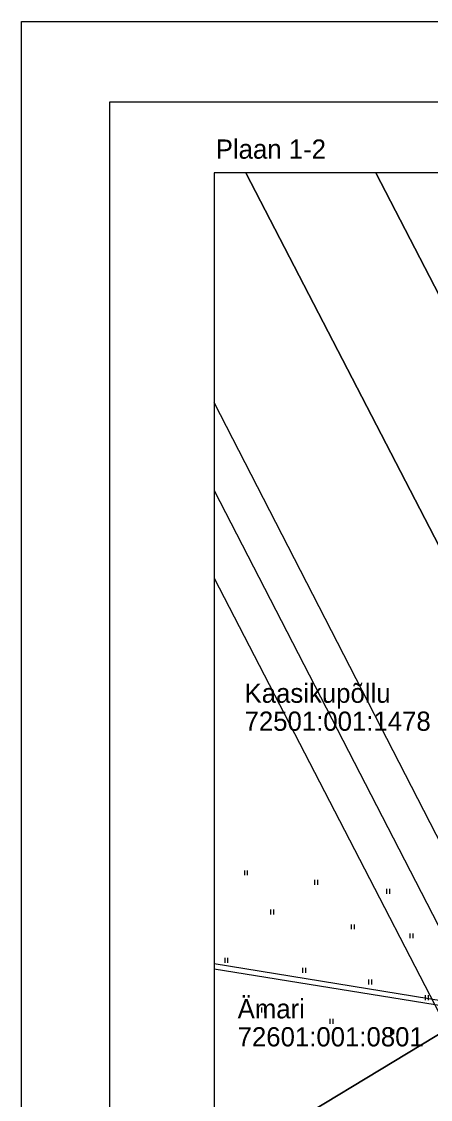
# Model space of a CAD drawing. Extents: x 532656 to 533339, y 6581345 to 6581629.
# Drawn here: x 532655.8 to 532719.5, y 6581439.6 to 6581607.7 of the extents above; entities that cross this region are included whole.
import ezdxf

# ---------------------------------------------------------------- set-up
doc = ezdxf.new("R2010")
doc.units = 0
for name, color, linetype in [('HALJASTUS', 7, 'Continuous'), ('KPOHULIIN', 7, 'Continuous'), ('PIIR', 7, 'Continuous'), ('PR_SIDE', 7, 'Continuous'), ('VORMISTUS_1', 7, 'Continuous')]:
    doc.layers.add(name, color=color, linetype=linetype)

msp = doc.modelspace()

# ---------------------------------------------------------------- linework, layer by layer
at = {"layer": 'HALJASTUS'}
for p, q in [((532690.51, 6581475.33), (532690.51, 6581474.57)), ((532690.96, 6581475.33), (532690.96, 6581474.57)), ((532701.44, 6581473.85), (532701.44, 6581473.09)), ((532701.89, 6581473.85), (532701.89, 6581473.09)), ((532712.66, 6581472.45), (532712.66, 6581471.69)), ((532713.12, 6581472.45), (532713.12, 6581471.69)), ((532694.6, 6581469.2), (532694.6, 6581468.44)), ((532695.05, 6581469.2), (532695.05, 6581468.44)), ((532707.15, 6581466.91), (532707.15, 6581466.14)), ((532707.61, 6581466.91), (532707.61, 6581466.14)), ((532716.31, 6581465.5), (532716.31, 6581464.74)), ((532716.77, 6581465.5), (532716.77, 6581464.74)), ((532687.45, 6581461.69), (532687.45, 6581460.93)), ((532687.9, 6581461.69), (532687.9, 6581460.93)), ((532699.56, 6581460.13), (532699.56, 6581459.37)), ((532700.01, 6581460.13), (532700.01, 6581459.37)), ((532709.85, 6581458.31), (532709.85, 6581457.55)), ((532710.31, 6581458.31), (532710.31, 6581457.55)), ((532718.67, 6581455.86), (532718.67, 6581455.1)), ((532719.13, 6581455.86), (532719.13, 6581455.1)), ((532693.17, 6581453.94), (532693.17, 6581453.18)), ((532693.63, 6581453.94), (532693.63, 6581453.18)), ((532703.85, 6581452.16), (532703.85, 6581451.4)), ((532704.3, 6581452.16), (532704.3, 6581451.4)), ((532713.26, 6581450.52), (532713.26, 6581449.76)), ((532713.72, 6581450.52), (532713.72, 6581449.76))]:
    msp.add_line(p, q, dxfattribs=at)
at = {"layer": 'KPOHULIIN'}
for p, q in [((532761.68, 6581400.4), (532685.8, 6581548.33)), ((532685.8, 6581534.57), (532754.86, 6581400.4)), ((532685.8, 6581520.92), (532748.01, 6581400.4))]:
    msp.add_line(p, q, dxfattribs=at)
at = {"layer": 'PIIR'}
for points in [[(532690.74, 6581584.15), (532751.03, 6581467.56), (532726.7, 6581453.3), (532685.8, 6581459.92)], [(532710.97, 6581584.15), (532766.54, 6581476.67), (532751.03, 6581467.56), (532690.74, 6581584.15)], [(532997.7, 6581510.35), (532853.02, 6581527.38), (532766.54, 6581476.67), (532710.97, 6581584.15)], [(532685.8, 6581428.57), (532726.7, 6581453.3), (532685.8, 6581459.92)], [(532688.64, 6581400.4), (532765.26, 6581446.64), (532740.99, 6581450.83), (532726.7, 6581453.3), (532685.8, 6581428.57)]]:
    msp.add_lwpolyline(points, dxfattribs=at)
at = {"layer": 'PR_SIDE'}
msp.add_lwpolyline([(532685.8, 6581460.81), (532752.67, 6581449.89), (532752.64, 6581449.86), (532756.24, 6581452.32), (532771.22, 6581460.37), (532800.17, 6581478.56), (532838.61, 6581500.05), (532844.07, 6581501.83), (532856.14, 6581503.74), (532864.29, 6581503.71), (532878.64, 6581501.24), (532905.33, 6581498.02), (532934.77, 6581493.52), (532940.7, 6581499.68), (532975.83, 6581495.55), (532984.66, 6581494.39), (532991.64, 6581492.92), (533009.76, 6581491.73), (533020.32, 6581490.23)], dxfattribs=at)
at = {"layer": 'VORMISTUS_1'}
for points in [[(532655.8, 6581607.74), (533027.05, 6581607.74), (533027.05, 6581345.24), (532655.8, 6581345.24)], [(532669.55, 6581357.74), (532669.55, 6581595.24), (533013.3, 6581595.24), (533013.3, 6581357.74)], [(532669.55, 6581595.24), (533013.3, 6581595.24), (533013.3, 6581357.74), (532669.55, 6581357.74)], [(532997.7, 6581400.4), (532997.7, 6581584.15), (532685.8, 6581584.15), (532685.8, 6581400.4)]]:
    msp.add_lwpolyline(points, close=True, dxfattribs=at)
for points in [[(532685.8, 6581584.15), (532685.8, 6581400.4)], [(532997.7, 6581584.15), (532685.8, 6581584.15)]]:
    msp.add_lwpolyline(points, dxfattribs=at)

# ---------------------------------------------------------------- texts
at = {"layer": 'PIIR'}
for s, p in [('Kaasikupõllu', (532690.54, 6581501.47)), ('72501:001:1478', (532690.54, 6581497.1)), ('Ämari', (532689.46, 6581452.24)), ('72601:001:0801', (532689.46, 6581447.87))]:
    msp.add_text(s, height=3, dxfattribs=at).set_placement(p)
at = {"layer": 'VORMISTUS_1'}
msp.add_text('Plaan 1-2', height=3, rotation=360, dxfattribs=at).set_placement((532686.05, 6581586.34))

doc.saveas('drawing.dxf')
